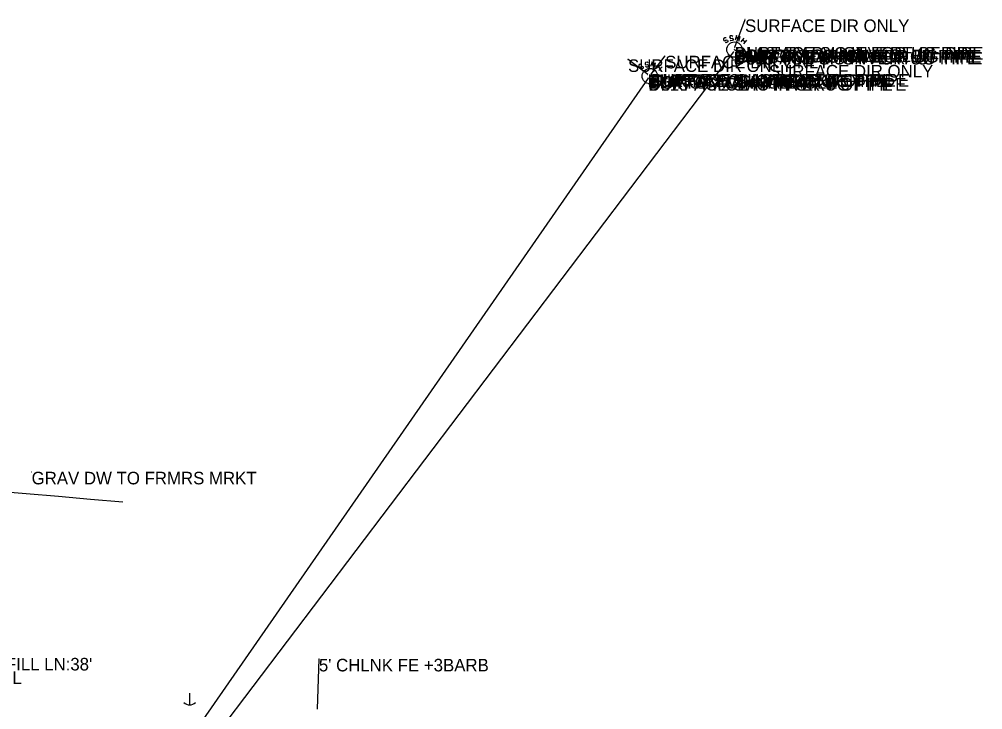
# Model space of a CAD drawing. Extents: x 929765 to 934279, y 1533086 to 1541189.
# Drawn here: x 932210.9 to 932594.3, y 1537591.7 to 1537866.4 of the extents above; entities that cross this region are included whole.
import ezdxf

# ---------------------------------------------------------------- set-up
doc = ezdxf.new("R2010")
doc.units = 0
for name, color, linetype in [('S_CROSS_DRAIN_ANNOT', 7, 'Continuous'), ('S_DRIVEWAY', 7, 'Continuous'), ('S_FENCE', 7, 'Continuous'), ('S_FENCE_ANNOT', 7, 'Continuous'), ('S_MANHOLE_ANNOT', 7, 'Continuous'), ('S_MSC_PT_SYM', 7, 'Continuous'), ('S_SANITARY_SEWER', 7, 'Continuous'), ('S_SANITARY_SEWER_ANNOT', 7, 'Continuous'), ('S_SURVEY_TEXT_ANNOT', 7, 'Continuous'), ('S_UTILITY_POLE', 7, 'Continuous'), ('S_UTL_PT_SYM', 7, 'Continuous')]:
    doc.layers.add(name, color=color, linetype=linetype)

msp = doc.modelspace()

# ---------------------------------------------------------------- linework, layer by layer
at = {"layer": 'S_DRIVEWAY'}
msp.add_lwpolyline([(932168.54, 1537606.85), (932172.06, 1537620.48), (932175.58, 1537634.11), (932179.11, 1537647.74), (932182.63, 1537661.37), (932191.72, 1537670.1), (932200.81, 1537678.82), (932213.61, 1537677.72), (932226.42, 1537676.61), (932239.22, 1537675.51), (932252.02, 1537674.4)], dxfattribs=at)
at = {"layer": 'S_FENCE'}
msp.add_lwpolyline([(932330.1, 1537611.94), (932329.46, 1537591.95)], dxfattribs=at)
msp.add_lwpolyline([(932330.1, 1537611.94), (932329.46, 1537591.95)], dxfattribs=at)
at = {"layer": 'S_MSC_PT_SYM'}
for points in [[(932495.13, 1537853.38), (932495.13, 1537853.43), (932495.13, 1537853.38), (932495.08, 1537853.38), (932495.13, 1537853.38), (932495.13, 1537853.33), (932495.13, 1537853.38), (932495.18, 1537853.38)], [(932495.59, 1537855.33), (932495.59, 1537855.38), (932495.59, 1537855.33), (932495.54, 1537855.33), (932495.59, 1537855.33), (932495.59, 1537855.28), (932495.59, 1537855.33), (932495.64, 1537855.33)], [(932496.47, 1537854.1), (932496.47, 1537854.15), (932496.47, 1537854.1), (932496.42, 1537854.1), (932496.47, 1537854.1), (932496.47, 1537854.05), (932496.47, 1537854.1), (932496.52, 1537854.1)], [(932460.96, 1537844.4), (932460.96, 1537844.45), (932460.96, 1537844.4), (932460.91, 1537844.4), (932460.96, 1537844.4), (932460.96, 1537844.35), (932460.96, 1537844.4), (932461.01, 1537844.4)], [(932461.19, 1537843), (932461.19, 1537843.05), (932461.19, 1537843), (932461.14, 1537843), (932461.19, 1537843), (932461.19, 1537842.95), (932461.19, 1537843), (932461.24, 1537843)], [(932462.33, 1537844.54), (932462.33, 1537844.59), (932462.33, 1537844.54), (932462.28, 1537844.54), (932462.33, 1537844.54), (932462.33, 1537844.49), (932462.33, 1537844.54), (932462.38, 1537844.54)], [(932215.79, 1537686.35), (932215.79, 1537686.4), (932215.79, 1537686.35), (932215.74, 1537686.35), (932215.79, 1537686.35), (932215.79, 1537686.3), (932215.79, 1537686.35), (932215.84, 1537686.35)], [(932330.1, 1537611.94), (932330.1, 1537611.99), (932330.1, 1537611.94), (932330.05, 1537611.94), (932330.1, 1537611.94), (932330.1, 1537611.89), (932330.1, 1537611.94), (932330.15, 1537611.94)]]:
    msp.add_lwpolyline(points, dxfattribs=at)
at = {"layer": 'S_SANITARY_SEWER'}
for p, q in [((932495.59, 1537855.33), (932499.68, 1537866.29)), ((932491.15, 1537858.61), (932491.07, 1537858.22)), ((932491.07, 1537858.22), (932491.26, 1537857.95)), ((932491.69, 1537859), (932491.15, 1537858.61)), ((932491.26, 1537857.95), (932491.69, 1537857.83)), ((932492.12, 1537858.92), (932491.69, 1537859)), ((932491.69, 1537857.83), (932492.23, 1537858.18)), ((932492.23, 1537857.02), (932491.85, 1537857.1)), ((932492.23, 1537858.18), (932492.7, 1537858.11)), ((932492.78, 1537857.41), (932492.23, 1537857.02)), ((932492.7, 1537858.11), (932492.85, 1537857.83)), ((932492.85, 1537857.83), (932492.78, 1537857.41)), ((932498.12, 1537857.37), (932499.36, 1537858.84)), ((932498.78, 1537858.14), (932499.75, 1537857.33)), ((932500.33, 1537858.03), (932499.09, 1537856.56)), ((932495.13, 1537853.38), (932256.2, 1537538.23)), ((932496.47, 1537854.1), (932509.22, 1537848.21)), ((932460.96, 1537844.4), (932453.13, 1537850.41)), ((932462.33, 1537844.54), (932467.91, 1537851.83)), ((932457.47, 1537848.07), (932457.4, 1537847.69)), ((932457.4, 1537847.69), (932457.59, 1537847.41)), ((932458.02, 1537848.46), (932457.47, 1537848.07)), ((932457.59, 1537847.41), (932458.02, 1537847.3)), ((932458.44, 1537848.38), (932458.02, 1537848.46)), ((932458.02, 1537847.3), (932458.56, 1537847.65)), ((932458.56, 1537846.48), (932458.17, 1537846.56)), ((932458.56, 1537847.65), (932459.02, 1537847.57)), ((932459.1, 1537846.87), (932458.56, 1537846.48)), ((932459.02, 1537847.57), (932459.18, 1537847.3)), ((932459.18, 1537847.3), (932459.1, 1537846.87)), ((932464.45, 1537846.83), (932465.69, 1537848.31)), ((932465.11, 1537847.61), (932466.08, 1537846.79)), ((932466.66, 1537847.49), (932465.42, 1537846.02)), ((932461.19, 1537843), (932237.41, 1537520.73))]:
    msp.add_line(p, q, dxfattribs=at)
for points in [[(932494.79, 1537859.54), (932494.44, 1537859.81), (932493.78, 1537859.73), (932493.55, 1537859.38), (932493.59, 1537859.07), (932493.94, 1537858.76), (932494.56, 1537858.88), (932494.95, 1537858.57), (932494.98, 1537858.26), (932494.71, 1537857.87), (932494.09, 1537857.8), (932493.74, 1537858.07)], [(932497.23, 1537857.68), (932497.77, 1537859.54), (932496.73, 1537858.53), (932496.34, 1537859.97), (932495.8, 1537858.11)], [(932463.56, 1537847.14), (932464.1, 1537849), (932463.05, 1537848), (932462.67, 1537849.43), (932462.12, 1537847.57)], [(932461.12, 1537849), (932460.77, 1537849.27), (932460.11, 1537849.2), (932459.88, 1537848.85), (932459.91, 1537848.54), (932460.26, 1537848.23), (932460.88, 1537848.34), (932461.27, 1537848.03), (932461.31, 1537847.72), (932461.04, 1537847.34), (932460.42, 1537847.26), (932460.07, 1537847.53)]]:
    msp.add_lwpolyline(points, dxfattribs=at)
for centre in [(932495.47, 1537854.31), (932461.8, 1537843.77)]:
    msp.add_circle(centre, 3.05, dxfattribs=at)
at = {"layer": 'S_UTILITY_POLE'}
msp.add_line((932278.61, 1537598.35), (932278.61, 1537593.62), dxfattribs=at)
msp.add_arc((932278.67, 1537597.05), 3.41, 226.3972, 313.6028, dxfattribs=at)
at = {"layer": 'S_UTL_PT_SYM'}
for points in [[(932499.68, 1537866.29), (932499.68, 1537866.34), (932499.68, 1537866.29), (932499.63, 1537866.29), (932499.68, 1537866.29), (932499.68, 1537866.24), (932499.68, 1537866.29), (932499.73, 1537866.29)], [(932495.13, 1537853.38), (932495.13, 1537853.43), (932495.13, 1537853.38), (932495.08, 1537853.38), (932495.13, 1537853.38), (932495.13, 1537853.33), (932495.13, 1537853.38), (932495.18, 1537853.38)], [(932495.47, 1537854.31), (932495.47, 1537854.36), (932495.47, 1537854.31), (932495.42, 1537854.31), (932495.47, 1537854.31), (932495.47, 1537854.26), (932495.47, 1537854.31), (932495.52, 1537854.31)], [(932495.59, 1537855.33), (932495.59, 1537855.38), (932495.59, 1537855.33), (932495.54, 1537855.33), (932495.59, 1537855.33), (932495.59, 1537855.28), (932495.59, 1537855.33), (932495.64, 1537855.33)], [(932496.47, 1537854.1), (932496.47, 1537854.15), (932496.47, 1537854.1), (932496.42, 1537854.1), (932496.47, 1537854.1), (932496.47, 1537854.05), (932496.47, 1537854.1), (932496.52, 1537854.1)], [(932453.13, 1537850.41), (932453.13, 1537850.46), (932453.13, 1537850.41), (932453.08, 1537850.41), (932453.13, 1537850.41), (932453.13, 1537850.36), (932453.13, 1537850.41), (932453.18, 1537850.41)], [(932467.91, 1537851.83), (932467.91, 1537851.88), (932467.91, 1537851.83), (932467.86, 1537851.83), (932467.91, 1537851.83), (932467.91, 1537851.78), (932467.91, 1537851.83), (932467.96, 1537851.83)], [(932509.22, 1537848.21), (932509.22, 1537848.26), (932509.22, 1537848.21), (932509.17, 1537848.21), (932509.22, 1537848.21), (932509.22, 1537848.16), (932509.22, 1537848.21), (932509.27, 1537848.21)], [(932460.96, 1537844.4), (932460.96, 1537844.45), (932460.96, 1537844.4), (932460.91, 1537844.4), (932460.96, 1537844.4), (932460.96, 1537844.35), (932460.96, 1537844.4), (932461.01, 1537844.4)], [(932461.19, 1537843), (932461.19, 1537843.05), (932461.19, 1537843), (932461.14, 1537843), (932461.19, 1537843), (932461.19, 1537842.95), (932461.19, 1537843), (932461.24, 1537843)], [(932461.8, 1537843.77), (932461.8, 1537843.82), (932461.8, 1537843.77), (932461.75, 1537843.77), (932461.8, 1537843.77), (932461.8, 1537843.72), (932461.8, 1537843.77), (932461.85, 1537843.77)], [(932462.33, 1537844.54), (932462.33, 1537844.59), (932462.33, 1537844.54), (932462.28, 1537844.54), (932462.33, 1537844.54), (932462.33, 1537844.49), (932462.33, 1537844.54), (932462.38, 1537844.54)]]:
    msp.add_lwpolyline(points, dxfattribs=at)

# ---------------------------------------------------------------- texts
at = {"layer": 'S_CROSS_DRAIN_ANNOT'}
for s, p in [("DI:12 TY:CPP CN:0% FILL LN:38'", (932138.66, 1537607.32)), ('CN:0% FILL', (932175.44, 1537601.97))]:
    msp.add_text(s, height=5, dxfattribs=at).set_placement(p)
at = {"layer": 'S_FENCE_ANNOT'}
msp.add_text("5' CHLNK FE +3BARB", height=5, dxfattribs=at).set_placement((932330.1, 1537606.94))
at = {"layer": 'S_MANHOLE_ANNOT'}
for p in [(932495.47, 1537849.31), (932461.8, 1537838.77)]:
    msp.add_text('BOTTOM OF MANHOLE', height=5, dxfattribs=at).set_placement(p)
at = {"layer": 'S_SANITARY_SEWER_ANNOT'}
for s, p in [('SURFACE DIR ONLY', (932499.68, 1537861.29)), ('TOP OF MANHOLE', (932495.47, 1537849.31)), ('DI:18" TY:PVC INVERT OF PIPE', (932495.13, 1537848.38)), ('DI:18" TY:PVC INVERT OF PIPE', (932495.59, 1537850.33)), ('DI:6" TY:PVC INVERT OF PIPE', (932496.47, 1537849.1)), ('SURFACE DIR ONLY', (932453.13, 1537845.41)), ('SURFACE DIR ONLY', (932467.91, 1537846.83)), ('SURFACE DIR ONLY', (932509.22, 1537843.21)), ('DI:6" TY:PVC INVERT OF PIPE', (932460.96, 1537839.4)), ('DI:15" TY:CLAY INVERT OF PIPE', (932461.19, 1537838)), ('TOP OF MANHOLE', (932461.8, 1537838.77)), ('DI:15" TY:CLAY INVERT OF PIPE', (932462.33, 1537839.54))]:
    msp.add_text(s, height=5, dxfattribs=at).set_placement(p)
at = {"layer": 'S_SURVEY_TEXT_ANNOT'}
for s, p in [('SURFACE SHOT FOR UG PIPE', (932495.13, 1537848.38)), ('SURFACE SHOT FOR UG PIPE', (932495.59, 1537850.33)), ('SURFACE SHOT FOR UG PIPE', (932496.47, 1537849.1)), ('SURFACE SHOT FOR UG PIPE', (932460.96, 1537839.4)), ('SURFACE SHOT FOR UG PIPE', (932461.19, 1537838)), ('SURFACE SHOT FOR UG PIPE', (932462.33, 1537839.54)), ('GRAV DW TO FRMRS MRKT', (932215.79, 1537681.35))]:
    msp.add_text(s, height=5, dxfattribs=at).set_placement(p)

doc.saveas('drawing.dxf')
